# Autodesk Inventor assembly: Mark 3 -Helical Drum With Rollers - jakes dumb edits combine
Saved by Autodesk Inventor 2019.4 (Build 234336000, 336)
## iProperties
Created: 2020-06
Part Number: Mark 3 -Helical Drum With Rollers - jakes dumb edits combine
Document SubType Name: Assembly
Designer: Administrator
Title: Mark 3 -Helical Drum With Rollers - jakes dumb edits combine v6
Author: Administrator
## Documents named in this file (2)
- c:\worker\convert-fusion-r04\tmp\job-1\561\output\files\d5a650f0-a4a9-40ee-bbf5-258857907a50\d20037ec-13f8-469e-bcb6-e2767c4b961f.iam
- c:\worker\convert-fusion-r04\tmp\job-1\561\output\files\d5a650f0-a4a9-40ee-bbf5-258857907a50\Mark 3 -Helical Drum With Rollers - jakes dumb edits combine v6.ipt
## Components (1 placed, 1 different names)
1. Mark 3 -Helical Drum With Rollers - jakes dumb edits combine v6
